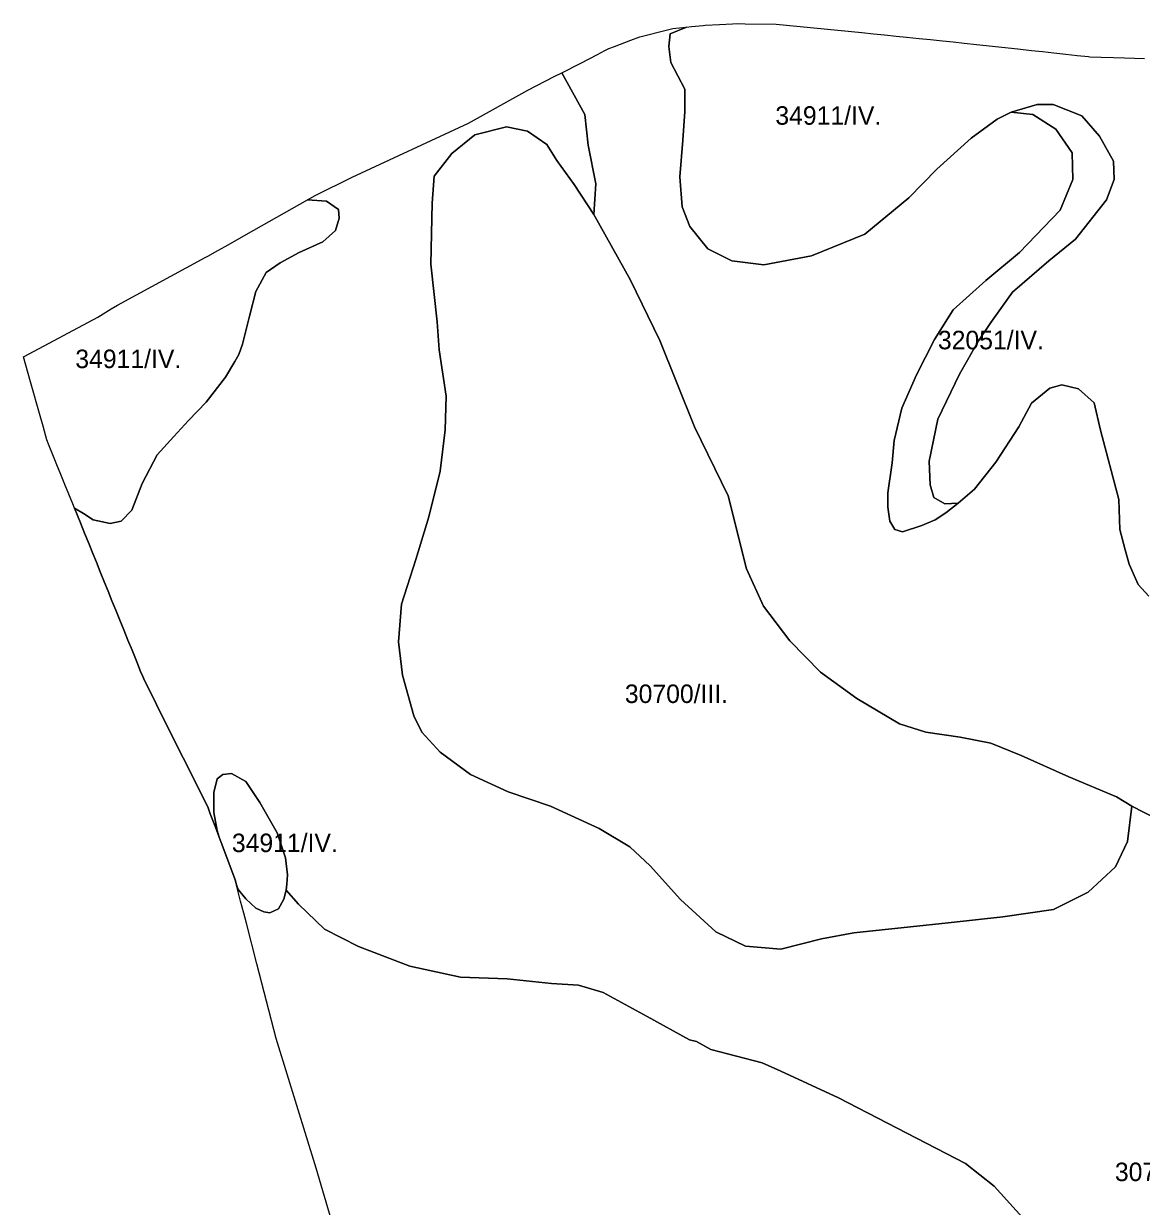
# Model space of a CAD drawing. Extents: x -521621 to -516761, y -1190184 to -1184927.
# Drawn here: x -521621 to -520715, y -1188092 to -1187133 of the extents above; entities that cross this region are included whole.
import ezdxf

# ---------------------------------------------------------------- set-up
doc = ezdxf.new("R2010")
doc.units = 0
doc.layers.add('BPEJ_s', color=7, linetype='Continuous')

msp = doc.modelspace()

# ---------------------------------------------------------------- linework, layer by layer
at = {"layer": 'BPEJ_s'}
for p, q in [((-521116.43, -1187142.72), (-521104.67, -1187139.74)), ((-521104.67, -1187139.74), (-521094.94, -1187137.28)), ((-521097.14, -1187141.62), (-521098.28, -1187151.84)), ((-521083.86, -1187136.13), (-521097.14, -1187141.62)), ((-521094.94, -1187137.28), (-521092.47, -1187137.03)), ((-521092.47, -1187137.03), (-521083.86, -1187136.13)), ((-521142.41, -1187151.9), (-521129.06, -1187146.84)), ((-521129.06, -1187146.84), (-521121.76, -1187144.07)), ((-521121.76, -1187144.07), (-521116.43, -1187142.72)), ((-521098.28, -1187151.84), (-521096.58, -1187164.9)), ((-521169.68, -1187165.29), (-521155.97, -1187158.25)), ((-521155.97, -1187158.25), (-521150.1, -1187155.24)), ((-521150.1, -1187155.24), (-521146.86, -1187153.58)), ((-521146.86, -1187153.58), (-521142.41, -1187151.9)), ((-521184.92, -1187173.11), (-521169.68, -1187165.29)), ((-521096.58, -1187164.9), (-521085.23, -1187186.48)), ((-521166.37, -1187206.92), (-521184.92, -1187173.11)), ((-521085.23, -1187186.48), (-521085.23, -1187204.65)), ((-521163.54, -1187231.9), (-521166.37, -1187206.92)), ((-521085.23, -1187204.65), (-521086.93, -1187227.93)), ((-520832.13, -1187210.89), (-520820.78, -1187205.21)), ((-520820.78, -1187205.21), (-520803.19, -1187206.92)), ((-520803.19, -1187206.92), (-520784.47, -1187218.84)), ((-520853.13, -1187226.22), (-520832.13, -1187210.89)), ((-520784.47, -1187218.84), (-520771.41, -1187238.15)), ((-521086.93, -1187227.93), (-521089.2, -1187257.45)), ((-520880.93, -1187251.21), (-520853.13, -1187226.22)), ((-521157.3, -1187263.13), (-521163.54, -1187231.9)), ((-520771.41, -1187238.15), (-520770.85, -1187259.72)), ((-520903.63, -1187274.49), (-520880.93, -1187251.21)), ((-521159, -1187288.11), (-521157.3, -1187263.13)), ((-521089.2, -1187257.45), (-521087.5, -1187281.87)), ((-520770.85, -1187259.72), (-520781.06, -1187284.71)), ((-520939.39, -1187304.01), (-520903.63, -1187274.49)), ((-521087.5, -1187281.87), (-521081.25, -1187297.77)), ((-520781.06, -1187284.71), (-520813.97, -1187318.78)), ((-521129.49, -1187340.92), (-521159, -1187288.11)), ((-521081.25, -1187297.77), (-521066.5, -1187315.94)), ((-520982.51, -1187321.62), (-520939.39, -1187304.01)), ((-521066.5, -1187315.94), (-521047.21, -1187325.59)), ((-521021.1, -1187329), (-520982.51, -1187321.62)), ((-520813.97, -1187318.78), (-520841.21, -1187341.49)), ((-521047.21, -1187325.59), (-521021.1, -1187329)), ((-521105.66, -1187390.32), (-521129.49, -1187340.92)), ((-520841.21, -1187341.49), (-520867.88, -1187365.34)), ((-520867.88, -1187365.34), (-520883.01, -1187389.38)), ((-521077.32, -1187460.13), (-521105.66, -1187390.32)), ((-520883.01, -1187389.38), (-520897.5, -1187418)), ((-520897.5, -1187418), (-520909.25, -1187445.04)), ((-520804.28, -1187441.12), (-520789.39, -1187428.97)), ((-520789.39, -1187428.97), (-520779.6, -1187426.23)), ((-520779.6, -1187426.23), (-520766.28, -1187429.36)), ((-520766.28, -1187429.36), (-520753.36, -1187440.73)), ((-520909.25, -1187445.04), (-520915.52, -1187471.3)), ((-520814.46, -1187460.33), (-520804.28, -1187441.12)), ((-520753.36, -1187440.73), (-520748.27, -1187463.07)), ((-521050.19, -1187516.05), (-521077.32, -1187460.13)), ((-520833.26, -1187488.94), (-520814.46, -1187460.33)), ((-520748.27, -1187463.07), (-520733.38, -1187519.12)), ((-520915.52, -1187471.3), (-520917.09, -1187489.33)), ((-520917.09, -1187489.33), (-520920.61, -1187513.63)), ((-520850.5, -1187510.89), (-520833.26, -1187488.94)), ((-521035.4, -1187575.26), (-521050.19, -1187516.05)), ((-520920.61, -1187513.63), (-520920.61, -1187525.39)), ((-520863.82, -1187522.25), (-520850.5, -1187510.89)), ((-520920.61, -1187525.39), (-520919.05, -1187536.75)), ((-520873.61, -1187530.09), (-520863.82, -1187522.25)), ((-520733.38, -1187519.12), (-520732.6, -1187543.42)), ((-520882.23, -1187535.58), (-520873.61, -1187530.09)), ((-520919.05, -1187536.75), (-520915.13, -1187543.42)), ((-520915.13, -1187543.42), (-520908.86, -1187545.38)), ((-520908.86, -1187545.38), (-520893.19, -1187540.28)), ((-520893.19, -1187540.28), (-520882.23, -1187535.58)), ((-520732.6, -1187543.42), (-520728.29, -1187559.88)), ((-520728.29, -1187559.88), (-520725.15, -1187571.64)), ((-520725.15, -1187571.64), (-520717.71, -1187588.1)), ((-521021.43, -1187605.69), (-521035.4, -1187575.26)), ((-520717.71, -1187588.1), (-520709.09, -1187597.5)), ((-521000.06, -1187633.65), (-521021.43, -1187605.69)), ((-520975.4, -1187659.15), (-521000.06, -1187633.65)), ((-520945.81, -1187680.53), (-520975.4, -1187659.15)), ((-520911.29, -1187701.09), (-520945.81, -1187680.53)), ((-520889.93, -1187707.67), (-520911.29, -1187701.09)), ((-520861.98, -1187711.78), (-520889.93, -1187707.67)), ((-520837.32, -1187716.72), (-520861.98, -1187711.78)), ((-520812.67, -1187726.58), (-520837.32, -1187716.72)), ((-520774.04, -1187743.85), (-520812.67, -1187726.58)), ((-520735.41, -1187760.3), (-520774.04, -1187743.85)), ((-520723.08, -1187767.71), (-520735.41, -1187760.3)), ((-520702.53, -1187778.4), (-520723.08, -1187767.71))]:
    msp.add_line(p, q, dxfattribs=at)
for points in [[(-520709.09, -1187597.5), (-520717.71, -1187588.1), (-520725.15, -1187571.64), (-520728.29, -1187559.88), (-520732.6, -1187543.42), (-520733.38, -1187519.12), (-520748.27, -1187463.07), (-520753.36, -1187440.73), (-520766.28, -1187429.36), (-520779.6, -1187426.23), (-520789.39, -1187428.97), (-520804.28, -1187441.12), (-520814.46, -1187460.33), (-520833.26, -1187488.94), (-520850.5, -1187510.89), (-520863.82, -1187522.25), (-520874.39, -1187522.64), (-520883.4, -1187517.55), (-520886.54, -1187507.36), (-520887.32, -1187488.15), (-520880.27, -1187454.05), (-520862.64, -1187417.6), (-520847.37, -1187390.56), (-520837.24, -1187375.56), (-520819.65, -1187351.14), (-520790.14, -1187325.59), (-520768.58, -1187307.99), (-520743.61, -1187276.19), (-520737.36, -1187259.72), (-520737.93, -1187244.96), (-520749.28, -1187224.52), (-520763.47, -1187208.05), (-520786.74, -1187198.97), (-520799.79, -1187198.97), (-520820.78, -1187205.21), (-520832.13, -1187210.89), (-520853.13, -1187226.22), (-520880.93, -1187251.21), (-520903.63, -1187274.49), (-520939.39, -1187304.01), (-520982.51, -1187321.62), (-521021.1, -1187329), (-521047.21, -1187325.59), (-521066.5, -1187315.94), (-521081.25, -1187297.77), (-521087.5, -1187281.87), (-521089.2, -1187257.45), (-521086.93, -1187227.93), (-521085.23, -1187204.65), (-521085.23, -1187186.48), (-521096.58, -1187164.9), (-521098.28, -1187151.84), (-521097.14, -1187141.62), (-521083.86, -1187136.13), (-521079.87, -1187135.72), (-521070.36, -1187134.74), (-521068.74, -1187134.66), (-521057.08, -1187134.09), (-521046.69, -1187133.59), (-521042.18, -1187133.37), (-521036.43, -1187133.43), (-521011.32, -1187133.7), (-520941.75, -1187140.65), (-520932.28, -1187141.59), (-520923.44, -1187142.47), (-520914.04, -1187143.41), (-520905.54, -1187144.26), (-520895.29, -1187145.28), (-520886.24, -1187146.19), (-520876.38, -1187147.17), (-520867.83, -1187148.09), (-520858.82, -1187149.08), (-520848.97, -1187150.16), (-520815.24, -1187153.86), (-520804.3, -1187155.06), (-520795.33, -1187156.04), (-520786.18, -1187157.04), (-520776.33, -1187158.12), (-520767.17, -1187159.13), (-520758.16, -1187160.11), (-520757, -1187160.24), (-520747.8, -1187160.55), (-520737.71, -1187160.89), (-520728.89, -1187161.19), (-520720.83, -1187161.47), (-520712.78, -1187161.74)], [(-520804.04, -1188109.66), (-520834.55, -1188075.81), (-520857.72, -1188057.36), (-520960.58, -1188004.1), (-521007.45, -1187982.73), (-521022.67, -1187975.86), (-521064.14, -1187965.05), (-521075.92, -1187958.42), (-521081.56, -1187957.19), (-521115.69, -1187938.25), (-521151.49, -1187918.7), (-521171.39, -1187912.91), (-521193.22, -1187911.63), (-521229.18, -1187907.77), (-521267.06, -1187906.49), (-521308.16, -1187897.49), (-521349.89, -1187881.43), (-521377.32, -1187867.43), (-521398.31, -1187847.16), (-521408.32, -1187835.92), (-521407.83, -1187831.03), (-521407.35, -1187823.46), (-521409.05, -1187809.78), (-521415.65, -1187789.51), (-521429.8, -1187764.84), (-521441.03, -1187747.74), (-521452.75, -1187741.15), (-521459.83, -1187742.12), (-521464.22, -1187745.54), (-521467.15, -1187756.78), (-521467.15, -1187772.9), (-521465.79, -1187780.24), (-521464.43, -1187787.57), (-521462.79, -1187792.86), (-521465.79, -1187784.86), (-521469.93, -1187773.86), (-521472.03, -1187768.28), (-521491.89, -1187728.51), (-521511.75, -1187688.73), (-521515.18, -1187681.84), (-521519.66, -1187672.87), (-521523.76, -1187664.65), (-521524.71, -1187662.76), (-521526.41, -1187658.55), (-521529.52, -1187650.87), (-521533.35, -1187641.42), (-521536.69, -1187633.17), (-521540.03, -1187624.91), (-521543.28, -1187616.89), (-521546.48, -1187608.97), (-521549.63, -1187601.21), (-521552.79, -1187593.39), (-521555.61, -1187586.42), (-521559.07, -1187577.88), (-521562.23, -1187570.07), (-521565.12, -1187562.92), (-521568.15, -1187555.44), (-521571.8, -1187546.43), (-521575.22, -1187537.99), (-521579.99, -1187526.19), (-521572.68, -1187530.57), (-521564.74, -1187535.68), (-521551.12, -1187538.52), (-521542.04, -1187536.82), (-521533.53, -1187527.74), (-521525.02, -1187506.16), (-521513.1, -1187482.88), (-521499.48, -1187468.11), (-521487.56, -1187455.05), (-521473.38, -1187440.29), (-521457.49, -1187419.85), (-521450.11, -1187407.36), (-521446.71, -1187401.68), (-521443.87, -1187393.16), (-521438.19, -1187370.45), (-521433.09, -1187350.57), (-521424.58, -1187335.24), (-521413.23, -1187327.3), (-521397.9, -1187318.78), (-521378.61, -1187310.26), (-521368.4, -1187301.18), (-521365.56, -1187290.95), (-521366.12, -1187284.14), (-521375.77, -1187277.33), (-521390.98, -1187276.21), (-521384.86, -1187272.76), (-521354.91, -1187257.91), (-521260.49, -1187213.94), (-521212.57, -1187187.3), (-521191.12, -1187176.3), (-521184.92, -1187173.11), (-521166.37, -1187206.92), (-521163.54, -1187231.9), (-521157.3, -1187263.13), (-521159, -1187288.11), (-521174.89, -1187263.7), (-521189.07, -1187244.39), (-521197.02, -1187231.33), (-521212.91, -1187220.54), (-521229.93, -1187217.14), (-521255.47, -1187223.38), (-521274.19, -1187238.71), (-521288.38, -1187256.89), (-521290.08, -1187279.03), (-521291.22, -1187328.43), (-521286.11, -1187374.99), (-521284.41, -1187397.7), (-521278.68, -1187435.46), (-521279.5, -1187462.6), (-521283.61, -1187496.31), (-521292.65, -1187533.32), (-521303.34, -1187567.86), (-521314.84, -1187604.05), (-521317.31, -1187634.48), (-521314.02, -1187661.61), (-521304.98, -1187694.51), (-521298.41, -1187707.67), (-521283.61, -1187724.12), (-521258.95, -1187742.21), (-521228.54, -1187756.19), (-521194.03, -1187767.71), (-521154.57, -1187785.8), (-521129.92, -1187800.6), (-521113.48, -1187816.23), (-521088.82, -1187843.36), (-521060.06, -1187869.68), (-521036.22, -1187881.2), (-521007.46, -1187883.66), (-520974.58, -1187875.44), (-520948.28, -1187870.5), (-520902.25, -1187865.57), (-520871.84, -1187862.28), (-520827.46, -1187857.35), (-520786.37, -1187851.59), (-520758.42, -1187837.61), (-520736.23, -1187817.05), (-520726.37, -1187796.49), (-520723.08, -1187767.71), (-520702.53, -1187778.4)], [(-521339.28, -1188213.59), (-521383.96, -1188061.22), (-521415.49, -1187959.74), (-521416.43, -1187956.13), (-521432.15, -1187895.47), (-521440.63, -1187862.74), (-521442.8, -1187854.39), (-521445.31, -1187844.7), (-521446.43, -1187840.4), (-521447.54, -1187836.09), (-521448.75, -1187831.42), (-521449.77, -1187827.49), (-521457.42, -1187807.14), (-521461.13, -1187797.29), (-521462.79, -1187792.86), (-521465.79, -1187784.86), (-521469.93, -1187773.86), (-521472.03, -1187768.28), (-521511.75, -1187688.73), (-521515.18, -1187681.84), (-521519.66, -1187672.87), (-521523.76, -1187664.65), (-521524.71, -1187662.76), (-521526.41, -1187658.55), (-521529.52, -1187650.87), (-521533.35, -1187641.42), (-521536.69, -1187633.17), (-521540.03, -1187624.91), (-521543.28, -1187616.89), (-521546.48, -1187608.97), (-521549.63, -1187601.21), (-521552.79, -1187593.39), (-521555.61, -1187586.42), (-521559.07, -1187577.88), (-521562.23, -1187570.07), (-521565.12, -1187562.92), (-521568.15, -1187555.44), (-521571.8, -1187546.43), (-521575.22, -1187537.99), (-521579.99, -1187526.19), (-521575.22, -1187537.99), (-521571.8, -1187546.43), (-521568.15, -1187555.44), (-521565.12, -1187562.92), (-521562.23, -1187570.07), (-521559.07, -1187577.88), (-521555.61, -1187586.42), (-521552.79, -1187593.39), (-521549.63, -1187601.21), (-521546.48, -1187608.97), (-521543.28, -1187616.89), (-521540.03, -1187624.91), (-521536.69, -1187633.17), (-521533.35, -1187641.42), (-521529.52, -1187650.87), (-521526.41, -1187658.55), (-521524.71, -1187662.76), (-521523.76, -1187664.65), (-521519.66, -1187672.87), (-521515.18, -1187681.84), (-521511.75, -1187688.73), (-521472.03, -1187768.28), (-521469.93, -1187773.86), (-521465.79, -1187784.86), (-521462.79, -1187792.86), (-521461.13, -1187797.29), (-521457.42, -1187807.14), (-521449.77, -1187827.49), (-521448.75, -1187831.42), (-521447.34, -1187835.37), (-521441.03, -1187842.76), (-521432.98, -1187850.33), (-521426.39, -1187853.51), (-521421.75, -1187854.24), (-521414.67, -1187851.06), (-521410.28, -1187843.25), (-521408.32, -1187835.92), (-521398.31, -1187847.16), (-521377.32, -1187867.43), (-521349.89, -1187881.43), (-521308.16, -1187897.49), (-521267.06, -1187906.49), (-521229.18, -1187907.77), (-521193.22, -1187911.63), (-521171.39, -1187912.91), (-521151.49, -1187918.7), (-521115.69, -1187938.25), (-521081.56, -1187957.19), (-521075.92, -1187958.42), (-521064.14, -1187965.05), (-521022.67, -1187975.86), (-521007.45, -1187982.73), (-520960.58, -1188004.1), (-520857.72, -1188057.36), (-520834.55, -1188075.81), (-520804.04, -1188109.66)]]:
    msp.add_lwpolyline(points, dxfattribs=at)
for points in [[(-520863.82, -1187522.25), (-520873.61, -1187530.09), (-520882.23, -1187535.58), (-520893.19, -1187540.28), (-520908.86, -1187545.38), (-520915.13, -1187543.42), (-520919.05, -1187536.75), (-520920.61, -1187525.39), (-520920.61, -1187513.63), (-520917.09, -1187489.33), (-520915.52, -1187471.3), (-520909.25, -1187445.04), (-520897.5, -1187418), (-520883.01, -1187389.38), (-520867.88, -1187365.34), (-520841.21, -1187341.49), (-520813.97, -1187318.78), (-520781.06, -1187284.71), (-520770.85, -1187259.72), (-520771.41, -1187238.15), (-520784.47, -1187218.84), (-520803.19, -1187206.92), (-520820.78, -1187205.21), (-520799.79, -1187198.97), (-520786.74, -1187198.97), (-520763.47, -1187208.05), (-520749.28, -1187224.52), (-520737.93, -1187244.96), (-520737.36, -1187259.72), (-520743.61, -1187276.19), (-520768.58, -1187307.99), (-520790.14, -1187325.59), (-520819.65, -1187351.14), (-520837.24, -1187375.56), (-520847.37, -1187390.56), (-520862.64, -1187417.6), (-520880.27, -1187454.05), (-520887.32, -1187488.15), (-520886.54, -1187507.36), (-520883.4, -1187517.55), (-520874.39, -1187522.64)], [(-521159, -1187288.11), (-521129.49, -1187340.92), (-521105.66, -1187390.32), (-521077.32, -1187460.13), (-521050.19, -1187516.05), (-521035.4, -1187575.26), (-521021.43, -1187605.69), (-521000.06, -1187633.65), (-520975.4, -1187659.15), (-520945.81, -1187680.53), (-520911.29, -1187701.09), (-520889.93, -1187707.67), (-520861.98, -1187711.78), (-520837.32, -1187716.72), (-520812.67, -1187726.58), (-520774.04, -1187743.85), (-520735.41, -1187760.3), (-520723.08, -1187767.71), (-520726.37, -1187796.49), (-520736.23, -1187817.05), (-520758.42, -1187837.61), (-520786.37, -1187851.59), (-520827.46, -1187857.35), (-520871.84, -1187862.28), (-520902.25, -1187865.57), (-520948.28, -1187870.5), (-520974.58, -1187875.44), (-521007.46, -1187883.66), (-521036.22, -1187881.2), (-521060.06, -1187869.68), (-521088.82, -1187843.36), (-521113.48, -1187816.23), (-521129.92, -1187800.6), (-521154.57, -1187785.8), (-521194.03, -1187767.71), (-521228.54, -1187756.19), (-521258.95, -1187742.21), (-521283.61, -1187724.12), (-521298.41, -1187707.67), (-521304.98, -1187694.51), (-521314.02, -1187661.61), (-521317.31, -1187634.48), (-521314.84, -1187604.05), (-521303.34, -1187567.86), (-521292.65, -1187533.32), (-521283.61, -1187496.31), (-521279.5, -1187462.6), (-521278.68, -1187435.46), (-521284.41, -1187397.7), (-521286.11, -1187374.99), (-521291.22, -1187328.43), (-521290.08, -1187279.03), (-521288.38, -1187256.89), (-521274.19, -1187238.71), (-521255.47, -1187223.38), (-521229.93, -1187217.14), (-521212.91, -1187220.54), (-521197.02, -1187231.33), (-521189.07, -1187244.39), (-521174.89, -1187263.7)], [(-521579.99, -1187526.19), (-521581.39, -1187522.73), (-521584.63, -1187514.73), (-521587.77, -1187506.97), (-521591.09, -1187498.77), (-521594.21, -1187491.06), (-521597.5, -1187482.95), (-521600.48, -1187475.58), (-521602.41, -1187470.81), (-521603.21, -1187467.93), (-521605.47, -1187459.82), (-521607.85, -1187451.29), (-521615.52, -1187423.77), (-521621.18, -1187403.45), (-521620.81, -1187403.31), (-521560.98, -1187371.3), (-521550.33, -1187364.55), (-521545.02, -1187361.67), (-521473.93, -1187323.01), (-521471.88, -1187321.85), (-521463.92, -1187317.36), (-521457.85, -1187313.94), (-521434.73, -1187300.89), (-521409.8, -1187286.82), (-521390.98, -1187276.21), (-521375.77, -1187277.33), (-521366.12, -1187284.14), (-521365.56, -1187290.95), (-521368.4, -1187301.18), (-521378.61, -1187310.26), (-521397.9, -1187318.78), (-521413.23, -1187327.3), (-521424.58, -1187335.24), (-521433.09, -1187350.57), (-521438.19, -1187370.45), (-521443.87, -1187393.16), (-521446.71, -1187401.68), (-521450.11, -1187407.36), (-521457.49, -1187419.85), (-521473.38, -1187440.29), (-521487.56, -1187455.05), (-521499.48, -1187468.11), (-521513.1, -1187482.88), (-521525.02, -1187506.16), (-521533.53, -1187527.74), (-521542.04, -1187536.82), (-521551.12, -1187538.52), (-521564.74, -1187535.68), (-521572.68, -1187530.57)], [(-521408.32, -1187835.92), (-521410.28, -1187843.25), (-521414.67, -1187851.06), (-521421.75, -1187854.24), (-521426.39, -1187853.51), (-521432.98, -1187850.33), (-521441.03, -1187842.76), (-521447.34, -1187835.37), (-521448.75, -1187831.42), (-521449.77, -1187827.49), (-521457.42, -1187807.14), (-521461.13, -1187797.29), (-521462.79, -1187792.86), (-521464.43, -1187787.57), (-521465.79, -1187780.24), (-521467.15, -1187772.9), (-521467.15, -1187756.78), (-521464.22, -1187745.54), (-521459.83, -1187742.12), (-521452.75, -1187741.15), (-521441.03, -1187747.74), (-521429.8, -1187764.84), (-521415.65, -1187789.51), (-521409.05, -1187809.78), (-521407.35, -1187823.46), (-521407.83, -1187831.03)]]:
    msp.add_lwpolyline(points, close=True, dxfattribs=at)

# ---------------------------------------------------------------- texts
for s, p in [('34911/IV.', (-521011.89, -1187215.33)), ('32051/IV.', (-520880.14, -1187397.37)), ('34911/IV.', (-521579.31, -1187412.62)), ('30700/III.', (-521133.88, -1187684.13)), ('34911/IV.', (-521452.41, -1187805.03)), ('30710/III.', (-520736.67, -1188071.75))]:
    msp.add_text(s, height=15, dxfattribs=at).set_placement(p)

doc.saveas('drawing.dxf')
